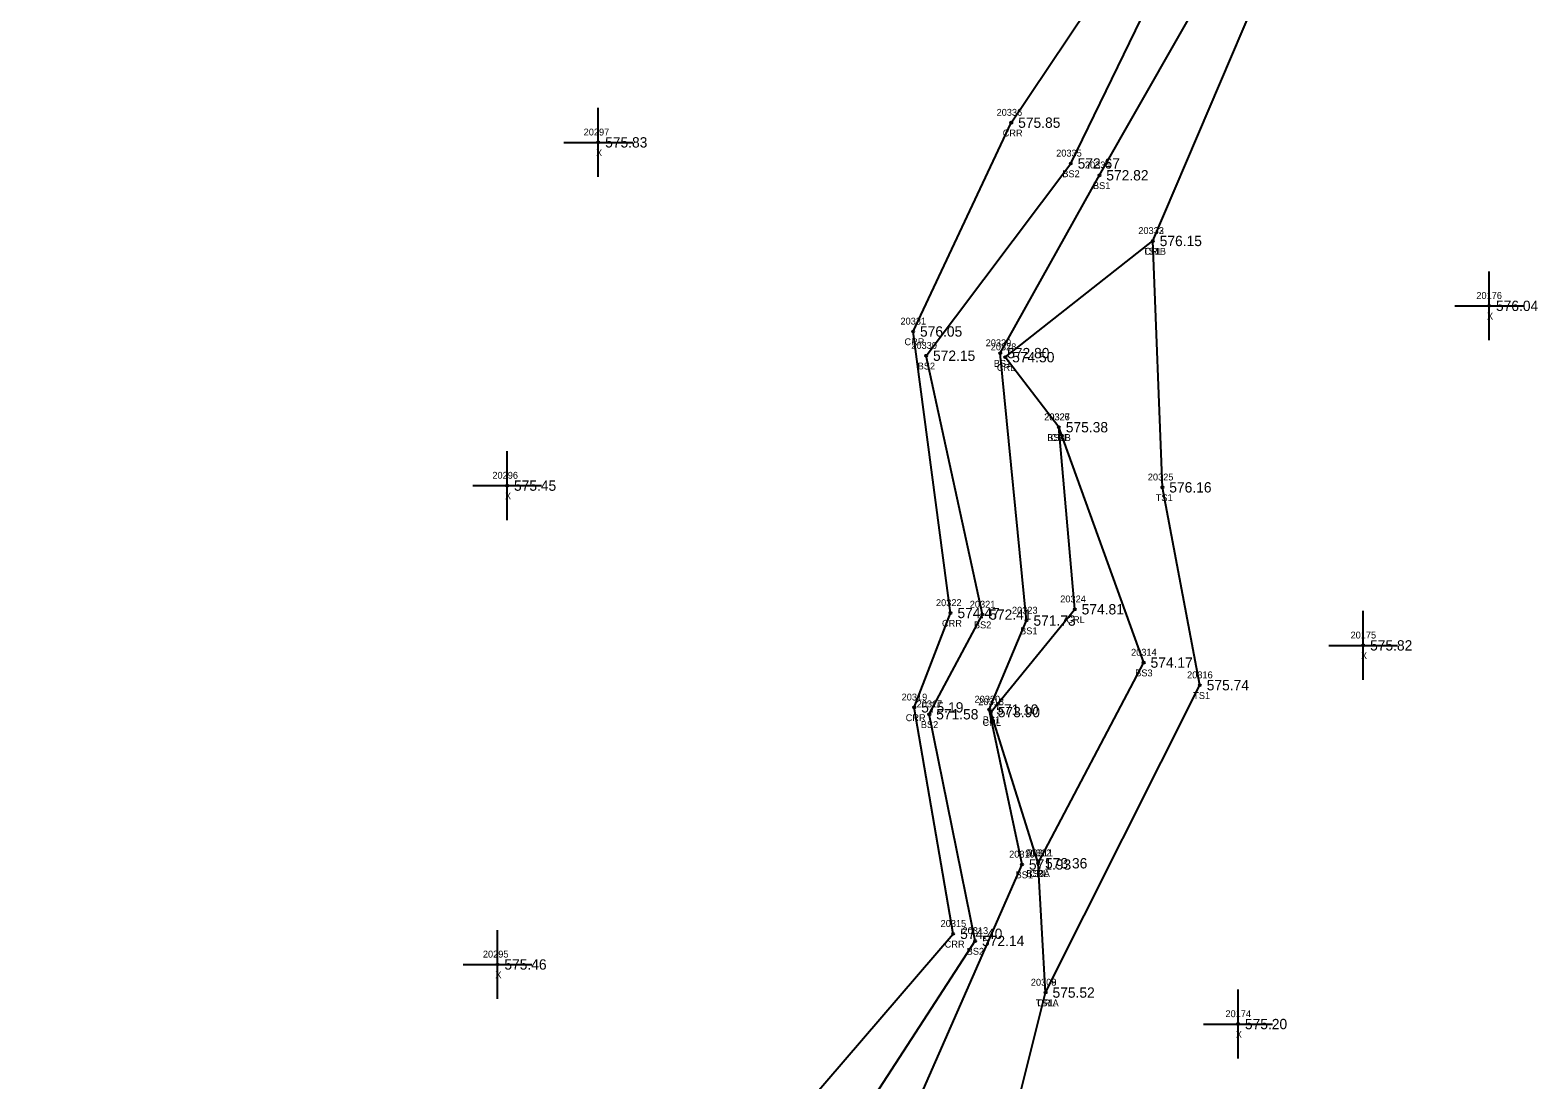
# Model space of a CAD drawing. Extents: x 1664837 to 1666270, y 987403 to 988245.
# Drawn here: x 1665511.2 to 1665730.3, y 987940.3 to 988092.7 of the extents above; entities that cross this region are included whole.
import ezdxf

# ---------------------------------------------------------------- set-up
doc = ezdxf.new("R2010")
doc.units = 0
for name, color, linetype in [('RD_DTM_BkLn2', 7, 'Continuous'), ('RD_DTM_BkLn_txCode', 7, 'Continuous'), ('RD_EX_H2O', 7, 'Continuous'), ('RD_EX_H2O_txCode', 7, 'Continuous'), ('RD_EX_Misc', 7, 'Continuous'), ('RD_EX_Misc_txCode', 7, 'Continuous'), ('RD_EX_TX_H2O_ELEV', 7, 'Continuous'), ('RD_EX_TX_Misc_ELEV', 7, 'Continuous'), ('RD_SMD_Locator', 7, 'Continuous')]:
    doc.layers.add(name, color=color, linetype=linetype)

msp = doc.modelspace()

# ---------------------------------------------------------------- linework, layer by layer
at = {"layer": 'RD_DTM_BkLn2'}
for points in [[(1665511.23, 987778.14), (1665517.66, 987789.45), (1665551.13, 987799.55), (1665566.94, 987815.17), (1665584.37, 987828.05), (1665587.06, 987846.74), (1665590.03, 987866.53), (1665606.32, 987897.21), (1665626.52, 987926.63), (1665648.51, 987960.46), (1665641.85, 987993.37), (1665649.56, 988007.84), (1665641.39, 988045.42), (1665662.4, 988073.33), (1665687.13, 988124.22), (1665718.46, 988169.29), (1665714.8, 988227.5)], [(1665573.38, 987803.15), (1665572.7, 987806.28), (1665588.73, 987824.67), (1665594.9, 987842.89), (1665595.52, 987863.7), (1665620.34, 987892.03), (1665633.86, 987922.65), (1665655.32, 987971.56), (1665650.57, 987994.06), (1665655.98, 988006.97), (1665652.16, 988045.8), (1665666.56, 988071.61), (1665695.3, 988121.96), (1665722.67, 988165.82), (1665720.98, 988226.06)], [(1665658.75, 987952.97), (1665681.15, 987997.59), (1665675.71, 988026.31), (1665674.32, 988062.08)], [(1665657.67, 987971.74), (1665672.99, 988000.87), (1665660.68, 988035.04)]]:
    msp.add_lwpolyline(points, dxfattribs=at)
at = {"layer": 'RD_EX_H2O'}
for points in [[(1665526.5, 987797.57), (1665535.59, 987808.2), (1665547.98, 987825.42), (1665568.59, 987829.69), (1665585.83, 987856.79), (1665584.87, 987866.91), (1665603.81, 987898.8), (1665618.99, 987930.85), (1665645.33, 987961.5), (1665639.67, 987994.37), (1665644.94, 988008.07), (1665639.5, 988048.94), (1665653.76, 988079.25), (1665684.31, 988124.82), (1665706.22, 988174.88), (1665711.8, 988227.54)], [(1665576.75, 987805.68), (1665589.55, 987821.56), (1665609.09, 987853.11), (1665622.95, 987890.58), (1665641.35, 987920.45), (1665654.29, 987935.19), (1665658.75, 987952.97), (1665657.67, 987971.74), (1665650.8, 987993.69), (1665662.98, 988008.61), (1665660.68, 988035.04), (1665652.89, 988045.21), (1665674.32, 988062.08), (1665698.86, 988119.64), (1665728.36, 988166.73), (1665725.83, 988226.06)]]:
    msp.add_lwpolyline(points, dxfattribs=at)
at = {"layer": 'RD_EX_Misc'}
for p, q in [((1665593.76, 988071.39), (1665593.76, 988081.39)), ((1665588.76, 988076.39), (1665598.76, 988076.39)), ((1665723.17, 988047.66), (1665723.17, 988057.66)), ((1665718.17, 988052.66), (1665728.17, 988052.66)), ((1665580.52, 988021.56), (1665580.52, 988031.56)), ((1665575.52, 988026.56), (1665585.52, 988026.56)), ((1665704.88, 987998.37), (1665704.88, 988008.37)), ((1665699.88, 988003.37), (1665709.88, 988003.37)), ((1665579.12, 987952.05), (1665579.12, 987962.05)), ((1665574.12, 987957.05), (1665584.12, 987957.05)), ((1665686.7, 987943.4), (1665686.7, 987953.4)), ((1665681.7, 987948.4), (1665691.7, 987948.4))]:
    msp.add_line(p, q, dxfattribs=at)
at = {"layer": 'RD_SMD_Locator'}
for centre in [(1665653.76, 988079.25), (1665593.76, 988076.39), (1665662.4, 988073.33), (1665666.56, 988071.61), (1665674.32, 988062.08), (1665674.32, 988062.08), (1665723.17, 988052.66), (1665639.5, 988048.94), (1665641.39, 988045.42), (1665652.16, 988045.8), (1665652.89, 988045.21), (1665660.68, 988035.04), (1665660.68, 988035.04), (1665580.52, 988026.56), (1665675.71, 988026.31), (1665644.94, 988008.07), (1665649.56, 988007.84), (1665655.98, 988006.97), (1665662.98, 988008.61), (1665704.88, 988003.37), (1665672.99, 988000.87), (1665681.15, 987997.59), (1665639.67, 987994.37), (1665650.57, 987994.06), (1665650.8, 987993.69), (1665641.85, 987993.37), (1665655.32, 987971.56), (1665657.67, 987971.74), (1665657.67, 987971.74), (1665645.33, 987961.5), (1665648.51, 987960.46), (1665579.12, 987957.05), (1665658.75, 987952.97), (1665658.75, 987952.97), (1665686.7, 987948.4)]:
    msp.add_circle(centre, 0.15, dxfattribs=at)

# ---------------------------------------------------------------- texts
at = {"layer": 'RD_DTM_BkLn_txCode'}
for s, p in [('20335', (1665660.28, 988074.33)), ('20334', (1665664.45, 988072.61)), ('BS2', (1665661.17, 988071.33)), ('BS1', (1665665.62, 988069.61)), ('20332', (1665672.21, 988063.08)), ('TS1B', (1665672.89, 988060.08)), ('20330', (1665639.24, 988046.42)), ('20329', (1665650.04, 988046.8)), ('BS2', (1665640.16, 988043.42)), ('BS1', (1665651.22, 988043.8)), ('20326', (1665658.53, 988036.04)), ('BS3B', (1665658.98, 988033.04)), ('20325', (1665673.59, 988027.31)), ('TS1', (1665674.75, 988024.31)), ('20321', (1665647.73, 988008.84)), ('20323', (1665653.86, 988007.97)), ('BS2', (1665648.33, 988005.84)), ('BS1', (1665655.04, 988004.97)), ('20314', (1665671.16, 988001.87)), ('BS3', (1665671.76, 987998.87)), ('20316', (1665679.3, 987998.59)), ('20320', (1665648.42, 987995.06)), ('TS1', (1665680.19, 987995.59)), ('20317', (1665640.01, 987994.37)), ('BS2', (1665640.62, 987991.37)), ('BS1', (1665649.63, 987992.06)), ('20310', (1665653.45, 987972.56)), ('20311', (1665656.11, 987972.74)), ('BS1', (1665654.38, 987969.56)), ('BS3A', (1665655.95, 987969.74)), ('20313', (1665646.68, 987961.46)), ('BS2', (1665647.28, 987958.46)), ('20309', (1665656.6, 987953.97)), ('TS1A', (1665657.3, 987950.97))]:
    msp.add_text(s, height=1, dxfattribs=at).set_placement(p)
at = {"layer": 'RD_EX_H2O_txCode'}
for s, p in [('20336', (1665651.62, 988080.25)), ('CRR', (1665652.51, 988077.25)), ('20333', (1665672.21, 988063.08)), ('CRL', (1665673.1, 988060.08)), ('20331', (1665637.66, 988049.94)), ('CRR', (1665638.24, 988046.94)), ('20328', (1665650.77, 988046.21)), ('CRL', (1665651.66, 988043.21)), ('20327', (1665658.56, 988036.04)), ('CRL', (1665659.45, 988033.04)), ('20322', (1665642.82, 988009.07)), ('20324', (1665660.87, 988009.61)), ('CRR', (1665643.69, 988006.07)), ('CRL', (1665661.76, 988006.61)), ('20319', (1665637.83, 987995.37)), ('20318', (1665648.97, 987994.69)), ('CRR', (1665638.42, 987992.37)), ('CRL', (1665649.58, 987991.69)), ('20312', (1665655.83, 987972.74)), ('CRL', (1665656.44, 987969.74)), ('20315', (1665643.49, 987962.5)), ('CRR', (1665644.08, 987959.5)), ('20308', (1665656.6, 987953.97)), ('CRL', (1665657.52, 987950.97))]:
    msp.add_text(s, height=1, dxfattribs=at).set_placement(p)
at = {"layer": 'RD_EX_Misc_txCode'}
for s, p in [('20297', (1665591.64, 988077.39)), ('X', (1665593.44, 988074.39)), ('20176', (1665721.32, 988053.66)), ('X', (1665722.86, 988050.66)), ('20296', (1665578.38, 988027.56)), ('X', (1665580.21, 988024.56)), ('20175', (1665703.04, 988004.37)), ('X', (1665704.56, 988001.37)), ('20295', (1665577, 987958.05)), ('X', (1665578.81, 987955.05)), ('20174', (1665684.87, 987949.4)), ('X', (1665686.38, 987946.4))]:
    msp.add_text(s, height=1, dxfattribs=at).set_placement(p)
at = {"layer": 'RD_EX_TX_H2O_ELEV'}
for s, p in [('575.85', (1665654.76, 988078.5)), ('576.15', (1665675.32, 988061.33)), ('576.05', (1665640.5, 988048.19)), ('574.50', (1665653.89, 988044.46)), ('575.38', (1665661.68, 988034.29)), ('574.81', (1665663.98, 988007.86)), ('574.47', (1665645.94, 988007.32)), ('575.19', (1665640.67, 987993.62)), ('573.90', (1665651.8, 987992.94)), ('573.36', (1665658.67, 987970.99)), ('574.40', (1665646.33, 987960.75)), ('575.52', (1665659.75, 987952.22))]:
    msp.add_text(s, height=1.5, dxfattribs=at).set_placement(p)
at = {"layer": 'RD_EX_TX_Misc_ELEV'}
for s, p in [('575.83', (1665594.76, 988075.64)), ('572.67', (1665663.4, 988072.58)), ('572.82', (1665667.56, 988070.86)), ('576.15', (1665675.32, 988061.33)), ('576.04', (1665724.17, 988051.91)), ('572.15', (1665642.39, 988044.67)), ('572.80', (1665653.16, 988045.05)), ('575.38', (1665661.68, 988034.29)), ('575.45', (1665581.52, 988025.81)), ('576.16', (1665676.71, 988025.56)), ('572.41', (1665650.56, 988007.09)), ('571.73', (1665656.98, 988006.22)), ('575.82', (1665705.88, 988002.62)), ('574.17', (1665673.99, 988000.12)), ('575.74', (1665682.15, 987996.84)), ('571.58', (1665642.85, 987992.62)), ('571.10', (1665651.57, 987993.31)), ('571.93', (1665656.32, 987970.81)), ('573.36', (1665658.67, 987970.99)), ('572.14', (1665649.51, 987959.71)), ('575.46', (1665580.12, 987956.3)), ('575.52', (1665659.75, 987952.22)), ('575.20', (1665687.7, 987947.65))]:
    msp.add_text(s, height=1.5, dxfattribs=at).set_placement(p)

doc.saveas('drawing.dxf')
